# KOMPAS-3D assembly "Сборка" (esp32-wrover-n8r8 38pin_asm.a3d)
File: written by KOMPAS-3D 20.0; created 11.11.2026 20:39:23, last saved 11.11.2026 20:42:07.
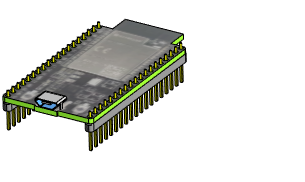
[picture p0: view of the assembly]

Document properties: Полное имя файла: D:\RicWork\Project-EPS32\box_compas\esp32\esp32-wrover-n8r8 38pin_asm.a3d

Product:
- Part/product: Сборка
    Масса: 0.021523
  - Component [detail]: Деталь  | Масса: 0.000213803; source file: ..\разъемы\USB-micro.m3d
  - Component [detail]: Деталь  | Масса: 0.016388; source file: esp32-wrover-n8r8 38pin.m3d
  - Component [detail]: Деталь  | qty 2  | Масса: 0.0024606; source file: ..\разъемы\pls_19.m3d

Referenced files in D:\RicWork\Project-EPS32\box_compas\esp32\: esp32-wrover-n8r8 38pin.m3d
Referenced files in D:\RicWork\Project-EPS32\box_compas\разъемы\: pls_19.m3d, USB-micro.m3d
Referenced files in D:\myProjects\Progect_esp32\box_compas\разъемы\: pls_19.m3d
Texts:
  Деталь (1)
  Деталь (2)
